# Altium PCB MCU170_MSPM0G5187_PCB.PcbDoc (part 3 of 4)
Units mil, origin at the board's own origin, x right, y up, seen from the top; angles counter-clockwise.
Board outline 2300 x 4450 mil, 4 copper layers (Top Layer, VCC Layer, GND Layer, Bottom Layer), stack 62.4 mil thick; 276 components, 190 nets, 913 pads, 323 vias.
Unrouted connection lines stored in the file: 4.
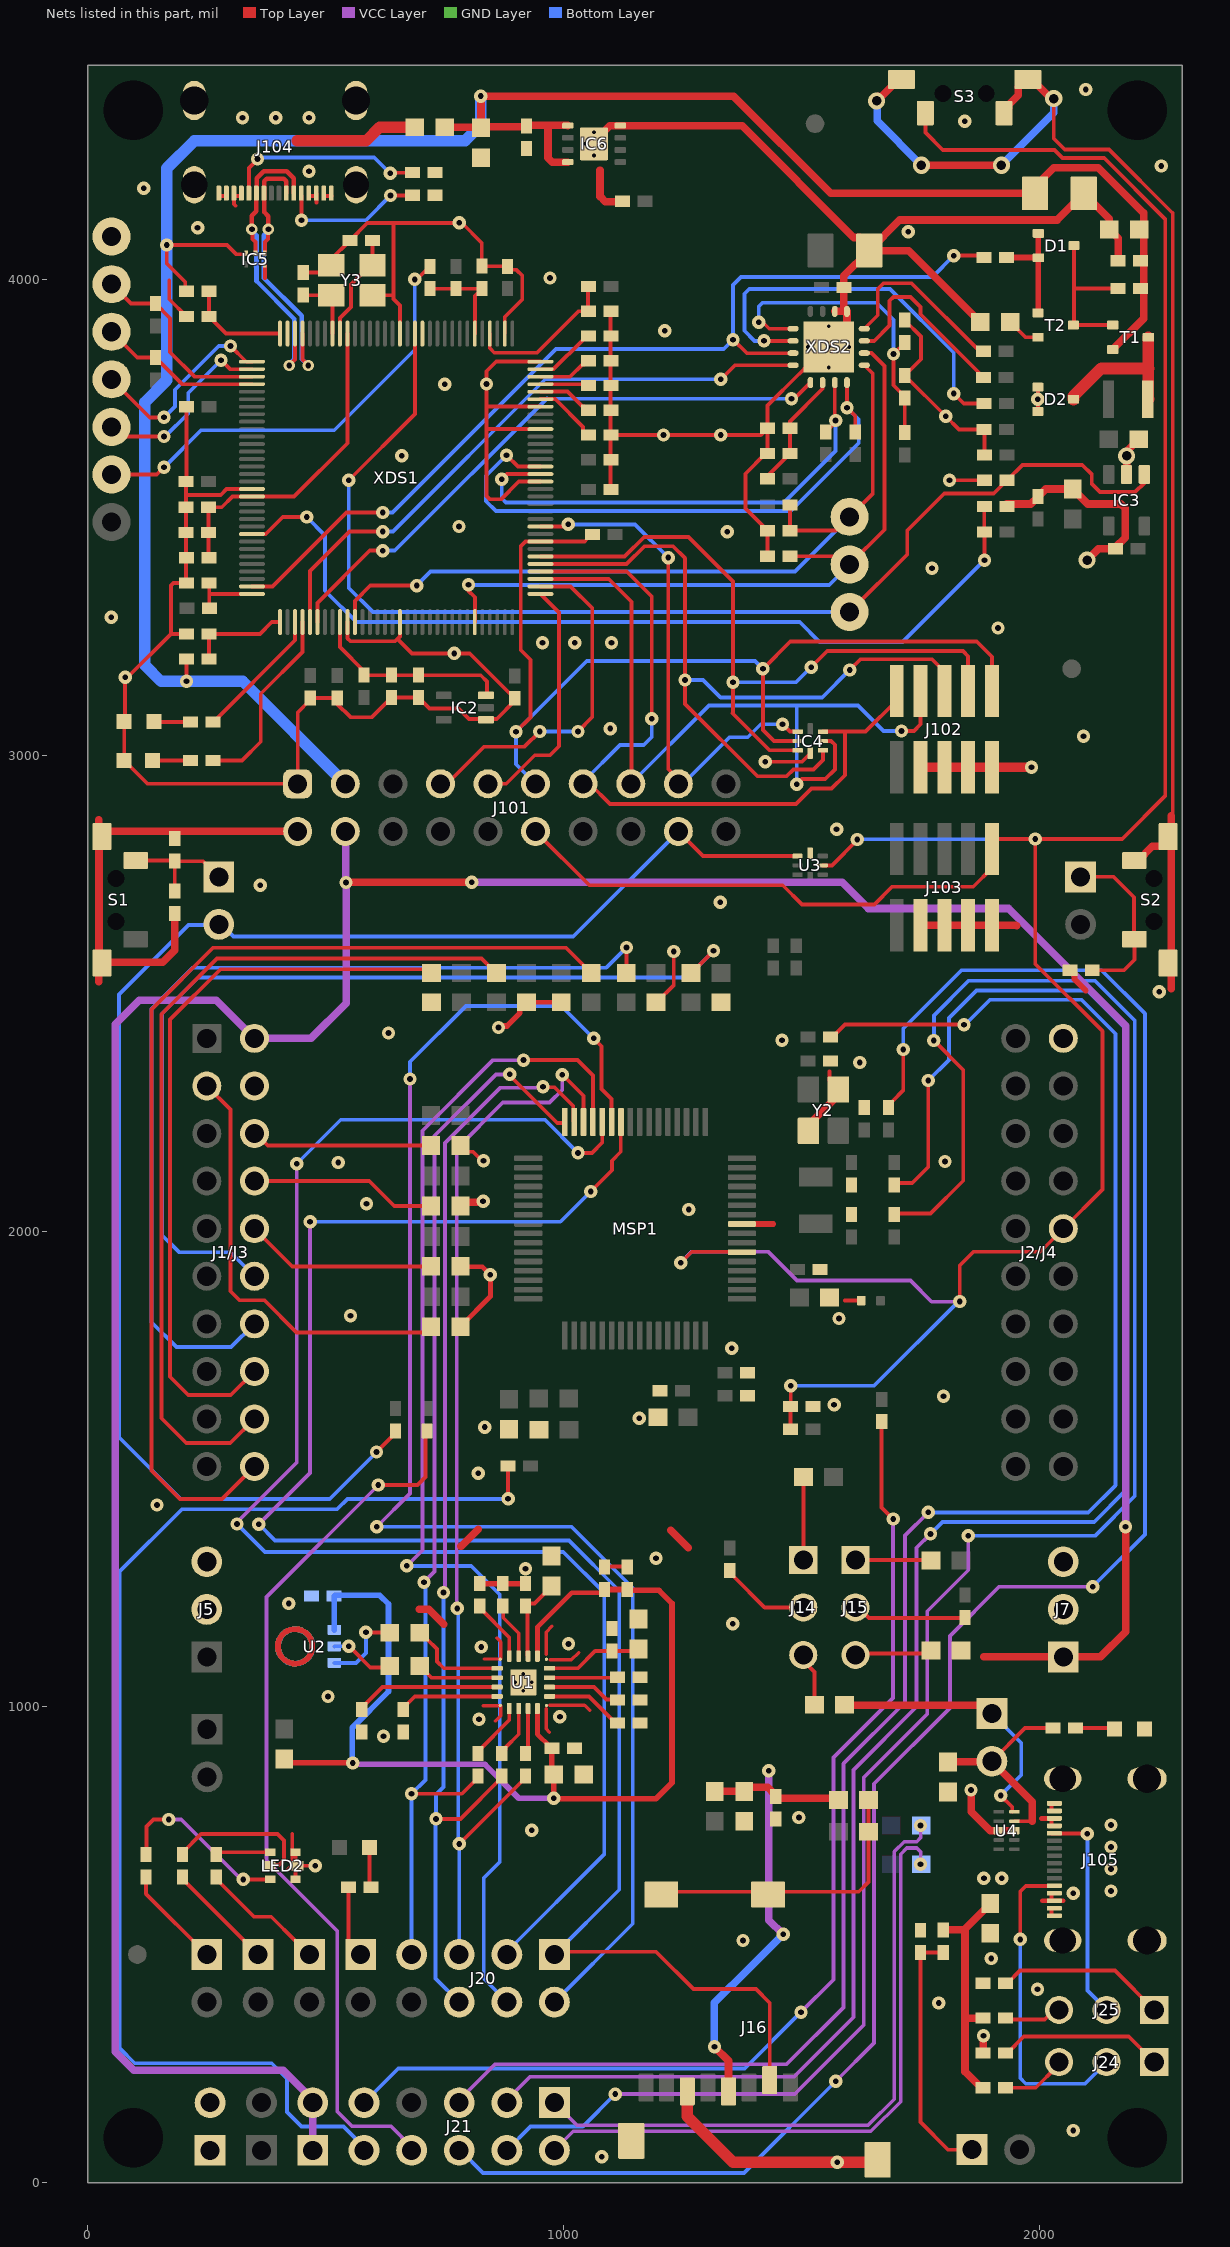
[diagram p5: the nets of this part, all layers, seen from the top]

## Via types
v1: diameter 28, hole 12, Top Layer to Bottom Layer, 291 vias
v2: diameter 19.68, hole 7.87, Top Layer to Bottom Layer, 9 vias
v3: diameter 36, hole 20, Top Layer to Bottom Layer, 8 vias
v4: diameter 24, hole 12, Top Layer to Bottom Layer, 4 vias
v5: diameter 24, hole 12, Top Layer to Bottom Layer, tented both sides, 4 vias
v6: diameter 19.68, hole 7.87, Top Layer to Bottom Layer, tented both sides, 4 vias
v7: diameter 28, hole 12, Top Layer to Bottom Layer, tented both sides, 2 vias
v8: diameter 39.37, hole 39.37, Top Layer to Bottom Layer, 1 vias

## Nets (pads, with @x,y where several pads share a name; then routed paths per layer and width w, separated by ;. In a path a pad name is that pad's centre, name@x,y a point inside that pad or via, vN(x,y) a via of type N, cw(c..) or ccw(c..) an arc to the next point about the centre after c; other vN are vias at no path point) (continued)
58_PB6_UC3_CS0_CTS: J16.2 J20.1 MSP1.58 | length 3766.4
  Top Layer w8: J20.1@980.54,479.62 986.32,485.4 1194.17,485.4 1272.67,406.9 1403.97,406.9 1433.07,377.8 J16.2@1433.07,215.7 ; v1(1056.83,2083.27) 1101.28,2127.72 1101.28,2147.83 1119.99,2166.55 MSP1.58@1119.99,2228.93
  VCC Layer w8: v1(359.28,1384.14) 360.02,1384.14 467.11,1491.23 v1(467.11,2019.48)
  Bottom Layer w8: v1(359.28,1384.14) 393.56,1349.87 1011.03,1349.87 1116.73,1244.16 1116.73,615.82 J20.1@980.54,479.62 ; v1(467.11,2019.48) 993.03,2019.48 v1(1056.83,2083.27)
59_PB7_UC3_POCI_RTS: J20.2 MSP1.59 | length 3190.3
  Top Layer w8: v1(1063.19,2404.94) 1079.75,2388.38 1079.75,2298.8 1100.81,2277.74 MSP1.59@1100.79,2229.41
  VCC Layer w8: v1(607.23,1378.75) 676.98,1448.51 676.98,2319.44 v1(677.08,2319.53)
  Bottom Layer w8: v1(607.23,1378.75) 1016.72,1378.75 1145.3,1250.17 1145.3,544.38 J20.2@980.54,379.62 ; v1(677.08,2319.53) 677.08,2355.79 794.55,2473.27 994.87,2473.27 v1(1063.19,2404.94)
60_PB8_UC3_PICO_TX: J20.3 MSP1.60 | length 3247.5
  Top Layer w8: v1(1030.16,2164.26) 1059.41,2164.26 1081.1,2185.95 MSP1.60@1081.1,2229.41
  VCC Layer w8: v1(313.4,1384.26) 313.4,1388.04 439.23,1513.87 v1(439.23,2141.48)
  Bottom Layer w8: v1(313.4,1384.26) 372.16,1325.51 999.25,1325.51 1085.49,1239.26 1085.49,690.51 880.54,485.55 J20.3@880.54,479.62 ; v1(439.23,2141.48) 531.68,2233.93 960.49,2233.93 v1(1030.16,2164.26)
61_PB9_UC3_SCK_RX: J20.4 MSP1.61 | length 2569.7
  Top Layer w8: v1(915.58,2359.31) 1029.37,2359.31 1061.42,2327.26 MSP1.61@1061.42,2229.41
  VCC Layer w8: v1(670.39,1296.38) 703.38,1329.36 703.38,2210.75 851.79,2359.16 915.43,2359.16 v1(915.58,2359.31)
  Bottom Layer w8: v1(670.39,1296.38) 805.75,1296.38 865.59,1236.54 865.59,673.73 831.98,640.13 831.98,429.39 880.54,380.84 J20.4@880.54,379.62
62_PB10_I2S_WCLK: J20.5 MSP1.62 R37.2 | length 2319.2
  Top Layer w8: v1(780.54,712.06) 919.61,851.13 R37.2@919.61,855.07 ; v1(997,2328.59) 997.68,2328.59 1041.73,2284.54 MSP1.62@1041.73,2229.41
  VCC Layer w8: v1(776.58,1206.98) 775.52,1208.03 775.52,2173.53 871.98,2269.99 970.45,2269.99 997,2296.54 v1(997,2328.59)
  Bottom Layer w8: v1(776.58,1206.98) 778.56,1205 778.56,714.04 v1(780.54,712.06) J20.5@780.54,479.62
63_PB11_I2S_BCLK: J20.6 MSP1.63 R39.2 | length 2380.1
  Top Layer w8: v1(731.75,764.61) 783.16,764.61 869.68,851.13 R39.2@869.68,855.07 ; v1(956.59,2303.23) 957.67,2302.15 980.5,2302.15 1020.14,2262.51 1020.14,2231.31 MSP1.63@1022.05,2229.41
  VCC Layer w8: v1@747.85,1240.91 750.72,1243.78 750.72,2184.85 867.24,2301.37 954.72,2301.37 v1(956.59,2303.23)
  Bottom Layer w8: v1(747.32,1240.37) 747.32,831.53 731.75,815.96 v1(731.75,764.61) 730.95,763.81 730.95,429.21 J20.6@780.54,379.62
64_PB12_I2S_AD0: J20.7 MSP1.64 R41.2 | length 2273.1
  Top Layer w8: v1(680.32,817.37) 786,817.37 811.94,843.32 819.76,851.13 R41.2@819.76,855.07 ; v1(886.78,2329.31) 886.78,2326.63 986.46,2226.96 1000.46,2226.96 1000.46,2227.5 MSP1.64@1002.36,2229.41
  VCC Layer w8: v1(706.48,1262.23) 728.53,1284.28 728.53,2200.27 857.57,2329.31 v1(886.78,2329.31)
  Bottom Layer w8: J20.7@680.54,479.62 680.43,479.73 680.43,817.27 v1(680.32,817.37) 709.39,846.44 709.39,1259.32 v1(706.48,1262.23)
+5V: J1/J3.21 J7.1 J17.1 J17.2 J22.1 J101.4 R12.2 R15.2 U4.5 | length 7574.5
  Top Layer w8: v1(1918.41,813.86) 1942.62,789.65 U4.5@1942.62,780
  Top Layer w16: v1(542.62,2732.62) 542.88,2732.89 806.86,2732.89 v1(807.13,2733.16) ; R12.2@1600,1003.78 1881.99,1003.78 J22.1@1900,985.77 ; 1882.48,1105 J7.1@2050,1105 2128.19,1105 2180.92,1157.73 v1(2180.92,1378.41)
  VCC Layer w16: J17.1@473.69,74 472.69,74 J17.2@472.69,168.18 472.69,174 410.44,236.26 96.43,236.26 57.81,274.88 57.81,2434.67 108.53,2485.39 269.61,2485.39 J1/J3.21@350,2405 468.98,2405 543.06,2479.08 543.06,2732.17 541.83,2733.41 541.83,2839.21 J101.4@541.04,2840 ; J17.1@497.17,49.52 J17.1@497.17,50.52 ; v1@807.29,2733 1585.48,2733 1640.49,2677.98 1934.75,2677.98 2180.92,2431.81 v1(2180.92,1378.41)
  Bottom Layer w8: J22.1@1900,985.77 1961.52,924.25 1961.52,856.97 v1(1918.41,813.86)
AREG: C28.2 C72.1 U1.17 | length 175.1
  Top Layer w8: C72.1@919.92,1210.96 924.24,1206.63 924.24,1107.58 U1.17@925.16,1106.66 ; C72.1@920.61,1211.65 926.28,1217.32 938.89,1217.32 959.77,1238.21 959.77,1238.45 967.72,1246.4 C28.2@974.71,1246.4
AVCCOUT: C55.1 R64.1 R65.2 XDS2.1 | length 692.2
  Top Layer w8: v1(1410,3910) 1418.48,3910 1432.09,3896.39 XDS2.1@1482.2,3896.39 ; R64.1@1717,3678.62 R65.2@1717,3751 1717,3753.89 1693.32,3777.58 v1(1693.32,3843.31) C55.1@1717,3867
  Bottom Layer w8: v1(1410,3910) 1410,3943 1418,3951 1657.64,3951 1693.32,3915.32 v1(1693.32,3843.31)
AVDD: C25.1 C27.1 C31.1 C73.1 C74.1 R38.1 U1.9 U1.16 U2.1 | length 2387.4
  Top Layer w10: U1.16@944.85,1106.66 944.85,1167.83 1017.14,1240.13 C73.1@1079.46,1240.13 ; U1.9@944.96,996.32 944.96,942.61 C74.1@970.65,916.92
  Top Layer w12: R38.1@412.97,890.35 420.83,882.49 556.36,882.49 v1(556.89,881.96) ; C74.1@975.1,913.16 975.1,862 C27.1@979.21,857.89 ; C27.1@981.95,857.89 979.45,855.39 v1(979.45,808.07) 980.65,806.87 1193.89,806.87 1227.73,840.72 1227.73,1217.59 1200.47,1244.86 1135.25,1244.86 C25.1@1133.72,1246.38 ; C73.1@1079.46,1240.13 C73.1@1085.71,1246.38 ; C73.1@1085.97,1246.63 C25.1@1133.47,1246.63
  VCC Layer w12: v1(556.89,881.96) 559.6,879.25 834.62,879.25 905.8,808.07 v1(979.45,808.07)
  Bottom Layer w10: v1@978.24,806.87 v1(979.45,808.07)
  Bottom Layer w12: U2.1@517.84,1161.82 517.84,1232.96 519.3,1234.42 613.67,1234.42 631.88,1216.21 631.88,1032.25 555.75,956.13 555.75,883.1 v1(556.89,881.96)
BSL_INVOKE: IC4.1 J101.17 XDS1.42 | length 1092.7
  Top Layer w8: XDS1.42@951.15,3480.64 1005.39,3480.64 v1(1009.88,3485.13) ; v1(1219.88,3415.34) 1219.88,2971.2 1241.04,2950.04 J101.17@1241.04,2940 ; v1(1460.08,3065) 1475.52,3049.56 IC4.1@1491.99,3049.56
  Bottom Layer w8: v1(1009.88,3485.13) 1150.09,3485.13 v1(1219.88,3415.34) ; J101.17@1241.04,2940 1251,2940 1348.76,3037.76 1387,3037.76 1414.24,3065 v1(1460.08,3065)
CC1: J24.2 J105.A5 | length 668.4
  Top Layer w8: v7(1959.42,511.35) 1959.42,612.17 1971.13,623.88 J105.A5@2025.17,623.88
  Bottom Layer w8: v7(1959.42,511.35) 1959.42,219.86 1971.28,208 2095.58,208 J24.2@2141.16,253.58
CC2: J25.2 J105.B5 | length 463
  Top Layer w8: J105.B5@2025.17,734.12 2025.43,733.86 2100.35,733.86 v7(2100.61,733.6)
  Bottom Layer w8: v7(2100.61,733.6) 2100.61,403.65 J25.2@2141.16,363.09
DCDCCAL0: R67.1 XDS2.12 | length 382.2
  Top Layer w8: XDS2.12@1631.8,3896.39 1660,3924.58 1660,3980 1672,3992 1731,3992 1873.8,3849.2 R67.1@1882.76,3849.2
DCDCCAL1: R66.1 XDS2.2 | length 846.7
  Top Layer w8: v1(1421.09,3870.8) XDS2.2@1482.2,3870.8 ; v1(1819.88,3760) 1840.88,3739 R66.1@1883.38,3739
  Bottom Layer w8: v1(1421.09,3870.8) 1401.2,3870.8 1380.01,3891.99 1380.01,3970.01 1390,3980 1685.86,3980 1819.88,3845.97 v1(1819.88,3760)
DCDCCAL2: R68.1 XDS2.11 | length 398.5
  Top Layer w8: XDS2.11@1631.8,3870.8 1652.8,3870.8 1685,3903 1685,3955 1693,3963 1729,3963 1750,3942 1750,3926.76 R68.1@1882.76,3794
DCDCIO0: XDS1.5 XDS2.4 | length 1301.6
  Top Layer w8: XDS1.5@466.9,3279.85 466.9,3386.9 550,3470 v1(620,3470) ; v1(1330.35,3790) 1359.97,3819.61 XDS2.4@1482.2,3819.61
  Bottom Layer w8: v1(620,3470) 641.3,3470 961.3,3790 v1(1330.35,3790)
DCDCIO1: XDS1.6 XDS2.5 | length 1268.8
  Top Layer w8: XDS1.6@482.65,3279.85 482.65,3320.15 ; 482.77,3320.15 482.77,3320.27 592.5,3430 v1(620,3430) ; v1(1479,3749) 1484.42,3749 XDS2.5@1518.61,3783.2
  Bottom Layer w8: v1(620,3430) 645,3430 965,3750 966,3749 v1(1479,3749)
DCDCPULSE: R75.2 XDS1.127 XDS2.3 | length 2033.7
  Top Layer w8: XDS1.127@344.85,3354.65 388.15,3354.65 543.5,3510 v1(620,3510) ; v1@1356,3874 1385.08,3844.92 1481.91,3844.92 XDS2.3@1482.2,3845.2 ; v1(1819.88,4050) 1879.38,4050 R75.2@1883.38,4046
  Bottom Layer w8: v1(620,3510) 640,3510 984,3854 1336.53,3854 v1(1356,3873.47) 1356,3988 1373,4005 1774.88,4005 v1(1819.88,4050)
DCDCRST: C59.1 R73.1 TP1.1 XDS1.11 XDS2.9 | length 1694.9
  Top Layer w8: XDS1.11@561.39,3279.85 561.39,3324.39 593.5,3356.5 v1(691,3356.5) ; R73.1@1475.62,3526 C59.1@1475.62,3472 1572,3472 TP1.1@1601,3501 1649.75,3549.75 1649.75,3801.66 XDS2.9@1631.8,3819.61
  Bottom Layer w8: v1(691,3356.5) 720.4,3385.9 1485.9,3385.9 TP1.1@1601,3501
DCDCTEST: R74.2 TP3.1 XDS1.27 XDS2.10 | length 1535.8
  Top Layer w8: v1(800,3358) 800,3345.3 813.35,3331.95 XDS1.27@813.35,3279.85 ; R74.2@1475.62,3418 1584,3418 TP3.1@1601,3401 1674,3474 1674,3818.34 1647.13,3845.2 XDS2.10@1631.8,3845.2
  Bottom Layer w8: v1(800,3358) 1558,3358 TP3.1@1601,3401
DREG: C29.2 C75.1 U1.14 | length 198.7
  Top Layer w8: U1.14@970.44,1081.07 1029.84,1081.07 1066.2,1117.44 1142.71,1117.44 1145.41,1120.14 C29.2@1145.41,1127.68
FMT0: R40.2 U1.19 | length 130.6
  Top Layer w8: R40.2@823.9,1211.65 823.9,1207.72 885.76,1145.86 U1.19@885.79,1106.66
GND: C1.2 C2.2 C3.2 C4.2 C5.2 C7.2 C8.1 C9.1 C10.2 C11.2 C12.2 C13.2 C14.1 C15.1 C16.1 C17.1 C18.1 C19.1 C20.1 C21.1 C22.1 C23.1 C24.1 C25.2 C26.1 C27.2 C28.1 C29.1 C31.2 C33.2 C34.2 C35.2 C36.2 C72.2 C73.2 C74.2 C75.2 C76.2 C77.2 J1/J3.22 J2/J4.20 J5.2 J5.3 J7.2 J7.3 J16.6 J16.9 J19.1 J19.2 J101.2 J103.3 J103.5 J103.7 J103.9 J105.1 J105.2 J105.3 J105.4 J105.A1 J105.A12 J105.B1 J105.B12 LED2.1 LED2.2 LED2.3 LED3.2 MSP1.41 R1.1 R3.1 R8.2 R40.1 R42.1 R43.1 R44.1 R46.1 R49.1 R50.1 S1.1 S1.2 S2.1 S2.2 S2.4 S3.1 S3.2 S3.3 U1.5 U1.10 U1.15 U1.20 U1.21 U2.4 U3.4 U4.3@1947.34,740.03 U4.8@1914.47,740.03 Y2.2 Y2.4 | length 7029.3
  Top Layer w7: 830.93,1002.47 866.25,1002.47 U1.5@866.79,1003.01 867.62,1002.17 867.62,981.7 856.26,970.34 ; 832.71,1100.58 U1.20@867.29,1100.58 ; 859.19,1144.81 867.54,1136.46 U1.20@867.54,1100.83 ; 963.1,995.77 963.1,953.55 970.17,946.48 ; 963.1,1110.39 963.1,1156.99 975.33,1169.23 ; 970.76,1003.79 1043.8,1003.79 1054.62,992.96 ; 971.81,1099.27 1016.47,1099.27 1031.45,1114.25
  Top Layer w8: 419.83,657.57 LED2.2@433.38,671.12 ; LED2.2@429.75,660.16 LED2.2@435.59,666 ; LED2.2@429.77,672.62 429.77,732.62 ; LED2.1@436.57,637.46 LED2.3@436.57,694.54 ; LED2.2@439.62,666.09 478.1,666.09 v1(478.19,666.18) ; C17.1@783.43,2179.75 796.53,2166.65 809.44,2166.65 v1@828.2,2147.89 ; C73.2@1083.92,1295.28 C25.2@1131.93,1295.28 ; C16.1@1194.31,2480.8 1195.29,2480.8 1231.54,2517.05 v1(1231.54,2587.6) ; 1558.86,2335.01 1558.86,2316 Y2.4@1577.5,2297.36 ; 1591.32,1853.76 R8.2@1625.44,1853.76 ; J105.B12@2025.17,560.89 J105.A1@2025.17,576.64 ; J105.B1@2025.17,781.36 J105.A12@2025.17,797.11 ; v3(2029.85,4379.85) 2030,4379.7 2030,4296 2053.13,4272.87 2146.29,4272.87 2280,4139.17 ; 2280,2879.16 2280,4139.17 ; 2280,4139.46 2280,4139.17
  Top Layer w10: C23.1@783.43,1798.83 783.43,1799.81 846.08,1862.47 846.08,1908.3 829.41,1924.97 784.26,1924.97 C21.1@783.43,1925.8 ; C20.1@921.69,2480.87 C22.1@995,2480.87
  Top Layer w11.81: R40.1@823.9,1258.9 C72.2@919.92,1258.9 ; 471.98,1127.17 ccw(c435.76,1127.17) 471.98,1127.17
  Top Layer w12: v1(863.12,2427.79) 866.19,2430.85 880.78,2430.85 908,2458.07 908,2468.17 920.7,2480.87 C20.1@921.69,2480.87 ; MSP1.41@1374.41,2014.84 1440.4,2014.84 ; C77.2@2063.62,2548.2 2067.56,2548.2 2073.37,2542.39 2073.37,2529.32 2097.08,2505.61
  Top Layer w15.75: v1(1856.17,825.21) 1856.17,780 1896.14,740.03 U4.3@1947.34,740.03
  Top Layer w16: 23.31,2523.62 23.31,2551.73 S1.2@34.74,2563.16 ; 23.34,2864.77 23.34,2840.3 S1.1@34.74,2828.91 ; S1.1@30.79,2824.95 23.38,2817.55 23.38,2574.52 S1.2@34.74,2563.16 ; S1.2@34.73,2577.06 S1.2@41.68,2570.1 ; S1.1@35.02,2828.63 S1.1@46.43,2840.03 ; S1.1@40.98,2840 J101.2@441.04,2840 J101.2@439.2,2838.16 ; R1.1@182.65,2665.07 182.65,2590.03 157.51,2564.88 36.46,2564.88 S1.2@34.74,2563.16 ; 696.11,1205 716.54,1205 748.09,1173.45 ; C19.1@783.43,2052.78 791.01,2060.36 828.4,2060.36 v1(830.69,2062.65) ; 784.32,1337.25 820.57,1373.5 ; 1225.13,1371.05 1262.08,1334.1 ; Y2.2@1520.45,2228.54 Y2.4@1568.53,2276.62 ; v3(1657.64,4375.12) 1661.46,4378.95 v3@1661.46,4385.15 ; v3@1658.11,4374.64 S3.2@1697.76,4414.29 ; S3.2@1701.11,4424.79 S3.2@1709.97,4424.79 ; J103.3@1750,2642.88 J103.5@1800,2642.88 J103.7@1850,2642.88 J103.9@1900,2642.88 1950.25,2642.88 1951.86,2641.28 ; v3@1752.32,4240.32 v3(1752,4240) v3(1920,4240) ; R50.1@1881.41,272.81 1881.92,273.31 1881.92,308.36 v1(1882.42,308.87) ; S3.3@1925.52,4353.93 1929.13,4353.93 1935.23,4360.03 1935.23,4367.03 1955.17,4386.97 1955.17,4404.25 S3.1@1975.71,4424.79 ; S3.1@1984.9,4418.95 1984.9,4417.98 1996.26,4406.62 1997.23,4406.62 2020.18,4383.67 2026.03,4383.67 v3(2029.85,4379.85) ; S2.4@2199.44,2778.68 2207.31,2778.68 2236.97,2808.33 2258.62,2808.33 2270.31,2820.02 S2.2@2270.31,2828.87 ; S2.1@2266.45,2558.13 2265.31,2558.13 S2.1@2270.31,2563.13 ; 2276.88,2509.14 S2.1@2276.88,2541.44 ; S2.1@2276.88,2581.55 2276.88,2872.41
  Top Layer w24: J16.6@1259.84,192.08 1259.84,139.2 1355.92,43.13 1654.59,43.13 J16.9@1659.84,48.38
  GND Layer w11.81: 471.98,1127.17 ccw(c435.76,1127.17) 471.98,1127.17
  Bottom Layer w16: v3(1657.64,4375.12) 1658.88,4373.87 1658.88,4333.12 v3(1752,4240) ; v3(1920,4240) 2029.85,4349.85 v3(2029.85,4379.85)
  other v1: 1575.24,43.13 1079.97,54.84 2071.08,109.71 1788.07,377.64 1995.63,406.9 1898.38,471.09 1376.75,509.12 933.04,740.75 1494.4,767.62 621.37,938.52 822.25,974.06 992.12,979.43 504.84,1022.02 826.98,1125.77 1010.21,1132.38 1355.48,1174.74 421.97,1217.29 919.79,1290.38 1194.17,1312.62 145.4,1424.21 820.5,1491.04 834.4,1588 1159.01,1606.89 1568.36,1634.86 1798.39,1653.09 1353.14,1753.82 1578.51,1816.15 552.16,1822.23 845.53,1908.3 1263.13,2045.42 585.56,2057.28 526.23,2144.03 1801.59,2146.33 831.61,2147.89 1622.2,2354.13 1458.86,2401.24 631.93,2416.39 2251.82,2502.77 1328.9,2690.8 362.59,2726.63 1573.61,2844.62
  other v6: 915.32,1033.83 897.6,1051.54 933.04,1051.54 915.32,1069.26
HOSTSCL: R70.1 XDS1.49 XDS2.7 | length 1051.7
  Top Layer w8: v1(870,3580.09) 880.78,3590.87 XDS1.49@951.15,3590.87 ; R70.1@1551,3678.98 1569.8,3697.77 XDS2.7@1569.8,3783.2
  Bottom Layer w8: v1(870,3580.09) 870,3540 879,3531 1463,3531 1571.5,3639.5 v1(1571.5,3703.35)
HOSTSDA: R69.1 XDS1.50 XDS2.8 | length 1241.2
  Top Layer w8: v1(880,3630.35) 903.73,3606.62 XDS1.50@951.15,3606.62 ; XDS2.8@1595.39,3783.2 v1(1595.39,3730) 1613,3712.39 R69.1@1613,3679.62
  Bottom Layer w8: v1(880,3630.35) 837.08,3587.44 837.08,3533.92 858,3513 1477.15,3513 1620.02,3655.87 1620.02,3705.37 v1(1595.39,3730)
IRSTN: R61.1 TP9.1 | length 936.7
  Top Layer w8: TP9.1@50,3590 145,3590 v1(160,3605) ; v1(687,4000) 691.24,4000 R61.1@718.87,4027.62
  Bottom Layer w8: v1(160,3605) 238,3683 517.85,3683 687,3852.15 v1(687,4000)
ITCK: R90.2 TP6.1 XDS1.100 | length 340.5
  Top Layer w8: TP6.1@50,3890 104,3836 R90.2@142,3836 198.15,3779.85 XDS1.100@344.85,3779.85
ITDI: TP8.1 XDS1.98 | length 402
  Top Layer w8: TP8.1@50,3690 70,3670 v1(160,3670) ; v1(280,3830) 298.65,3811.35 XDS1.98@344.85,3811.35
  Bottom Layer w8: v1(160,3670) 162.52,3670 211,3718.48 211,3761 v1(280,3830)
ITDO: TP7.1 XDS1.97 | length 424.3
  Top Layer w8: TP7.1@50,3790 130,3710 v1(160,3710) ; v1(300,3860) 332.91,3827.09 XDS1.97@344.85,3827.09
  Bottom Layer w8: v1(160,3710) 183,3733 183,3768 275,3860 v1(300,3860)
ITMS: R89.2 TP5.1 XDS1.99 | length 417.2
  Top Layer w8: TP5.1@50,3990 90.62,3949.38 R89.2@142,3949.38 173,3918.38 173,3847 224.4,3795.6 XDS1.99@344.85,3795.6
L_2_PB14_A0_21: J1/J3.23 R28.1 | length 381.7
  Top Layer w8: J1/J3.23@350,2205 352.99,2205 378.24,2179.75 R28.1@721.22,2179.75
L_3_PB15_A0_20: J1/J3.24 R30.1 | length 392.8
  Top Layer w8: J1/J3.24@350.13,2105.13 591.57,2105.13 643.92,2052.78 R30.1@721.22,2052.78
L_4_PB16_A0_19: J1/J3.25 R32.1 | length 403.7
  Top Layer w8: J1/J3.25@350,2005 429.69,1925.31 R32.1@720.73,1925.31
L_5_PA12_I2S_BCLK_A0_18: J1/J3.28 R31.1 | length 1561.3
  Top Layer w8: J1/J3.28@350,1705 300.42,1655.42 211.19,1655.42 172.74,1693.87 172.74,2444.65 278.48,2550.39 714.28,2550.39 R31.1@722.38,2542.28
L_6_PA13_I2S_AD0_A0_17: J1/J3.29 R33.1 | length 1851.9
  Top Layer w8: J1/J3.29@350,1605 299.43,1554.43 206.9,1554.43 154.67,1606.66 154.67,2455.55 271.69,2572.57 827.41,2572.57 857.71,2542.28 R33.1@858.69,2542.28
L_7_PA14_I2S_AD1_A0_16: J1/J3.30 R35.1 | length 2239.1
  Top Layer w8: J1/J3.30@350,1505 282.02,1437.02 193.49,1437.02 133.53,1496.98 133.53,2465.75 263.31,2595.53 1004.74,2595.53 1042.31,2557.96 1042.31,2556.98 1057.01,2542.28 R35.1@1058,2542.28
L_8_PA15_I2S_WCLK_A0_15: J1/J3.27 R29.1 | length 2021.7
  Top Layer w8: R29.1@1131.31,2542.28 1132.04,2543 v1(1132.04,2595.92)
  Bottom Layer w8: J1/J3.27@350,1805 301.14,1756.14 186.23,1756.14 133.87,1808.49 133.87,2466.39 221.05,2553.56 1089.68,2553.56 v1(1132.04,2595.92)
L_9_PA16_I2S_MCLK_A0_14: J1/J3.26 R36.1 | length 1976
  Top Layer w8: R36.1@1267.62,2542.34 1268.61,2542.34 1314.74,2588.48 v1(1314.74,2589.19)
  Bottom Layer w8: J1/J3.26@350,1905 299.36,1955.64 191.41,1955.64 156.57,1990.48 156.57,2457.51 232.21,2533.15 1259.53,2533.15 1314.74,2588.36 v1(1314.74,2589.19)
L_11_PA18_BSL_Invoke: J8.2 J101.18 R22.1 U3.5 | length 3237
  Top Layer w8: v1(606.56,1535.7) 606.9,1535.7 646.74,1575.54 R22.1@646.74,1579.48 ; J101.18@1241.04,2840 1292.87,2788.17 U3.5@1491.35,2788.17
  Bottom Layer w8: v1@606.56,1534.99 508.42,1436.85 195.15,1436.85 65.41,1566.59 65.41,2496.95 211.68,2643.23 273.96,2643.23 J8.2@275.18,2644.45 280.92,2644.45 306.19,2619.18 1020.22,2619.18 J101.18@1241.04,2840
L_26_PA25_A0_2: J1/J3.2 R34.1 | length 914.3
  Top Layer w8: J1/J3.2@250,2305 299.73,2255.27 299.73,1873.5 318.5,1854.72 371.16,1854.72 438.83,1787.05 709.45,1787.05 R34.1@721.22,1798.83
L_62_PB10_I2S_WCLK: R37.1 U1.8 | length 96
  Top Layer w8: R37.1@919.61,902.31 925.12,907.83 U1.8@925.12,996.03
L_63_PB11_I2S_BCLK: R39.1 U1.7 | length 108.9
  Top Layer w8: R39.1@869.68,902.31 877.49,910.12 877.49,914.38 905.48,942.36 U1.7@905.48,996.43
L_64_PB12_I2S_AD0: R41.1 U1.6 | length 121.5
  Top Layer w8: R41.1@819.76,902.31 819.76,906.25 885.79,972.29 U1.6@885.79,996.43
LS_17_PA21_VREF-: J21.8 R20.1 | length 1866.4
  Top Layer w8: v1(610.26,1466.41) 692.97,1466.41 709.39,1482.82 709.39,1576.12 R20.1@712.75,1579.48
  VCC Layer w8: v1@610.26,1465.94 375.21,1230.89 375.21,677.77 524.25,528.73 524.25,149.86 555.48,118.63 636.91,118.63 J21.8@680.54,75
LS_24_PA23_VREF+: J21.10 R21.1 | length 2591.6
  Top Layer w8: R21.1@882.87,1506.26 883.24,1505.89 v1(883.24,1437.18)
  Bottom Layer w8: J21.10@580.54,75 537.58,117.95 449.13,117.95 418.64,148.44 418.64,218.81 386.4,251.06 98.59,251.06 66.76,282.88 66.76,1284.4 197.7,1415.34 523.96,1415.34 545.81,1437.18 v1(883.24,1437.18)
LS_42_PA2_ROSC: J21.9 R9.1 | length 2337.1
  Top Layer w8: R9.1@1667.95,1608.05 1667.95,1419.26 v1(1692.44,1394.77)
  VCC Layer w8: v1(1498.89,358.5) 1566.96,426.57 1566.96,893.46 1692.44,1018.94 v1(1692.44,1394.77)
  Bottom Layer w8: J21.9@580.54,168.18 652.52,240.17 1380.56,240.17 v1(1498.89,358.5)
LS_43_PA3_LFXIN: J21.4 R10.1 | length 4406.9
  Top Layer w8: R10.1@1694.83,2029.79 1701.63,2036.59 1770.7,2036.59 1839.93,2105.82 1839.93,2338.72 v1(1778.01,2400.64)
  VCC Layer w8: v1(1108.38,186.25) 1485.73,186.25 1630.76,331.27 1630.76,851.88 1764.09,985.22 1764.09,1200.96 1850.27,1287.14 v1(1850.27,1359.47)
  Bottom Layer w8: J21.4@888.41,68.18 J21.4@880.54,68.18 930.54,118.18 1040.31,118.18 v1(1108.38,186.25) ; v1(1778.01,2400.64) 1778.01,2453 1851.09,2526.09 2116.72,2526.09 2200.21,2442.61 2200.21,1442.9 2116.78,1359.47 v1(1850.27,1359.47)
LS_44_PA4_LFXOUT: J21.3 R11.1 | length 4146.5
  Top Layer w8: R11.1@1694.83,2100.72 1732.68,2100.72 1766.24,2134.29 v1(1766.24,2316.33)
  VCC Layer w8: J21.3@880.54,174 929.09,222.55 1484.13,222.55 1609.21,347.64 1609.21,867.72 1741.7,1000.21 1741.7,1334.41 v1(1770.85,1363.56)
  Bottom Layer w8: v1(1766.24,2316.33) 1809.55,2359.63 1809.55,2447.5 1867.66,2505.61 2101.17,2505.61 2179.78,2427.01 2179.78,1453.48 2114.92,1388.62 1795.91,1388.62 v1(1770.85,1363.56)
LS_45_PA5_HFXIN: J21.6 R14.1 | length 4293.7
  Top Layer w8: R14.1@1682.61,2259.81 1690.42,2267.62 1690.42,2272.1 1713.49,2295.17 v1(1713.49,2381.47)
  VCC Layer w8: v1(1571.81,213.34) 1652.3,293.83 1652.3,838.35 1811.61,997.65 1811.61,1149.17 1915.05,1252.6 v1(2111.73,1252.6)
  Bottom Layer w8: J21.6@780.54,68.18 783.06,68.18 830.73,20.5 1378.97,20.5 v1(1571.81,213.34) ; v1(1713.49,2381.47) 1713.49,2425.31 1836.37,2548.2 2130.13,2548.2 2221.44,2456.89 2221.44,1362.31 v1(2111.73,1252.6)
LS_46_PA6_HFXOUT: J21.5 R17.1 | length 4034.4
  Top Layer w8: R17.1@1560.98,2408.02 1564.92,2408.02 1591.27,2434.37 1840.62,2434.37 v1(1841.35,2433.64)
  VCC Layer w8: J21.5@780.54,167.74 J21.5@783.66,170.87 ; J21.5@780.54,174 855.38,248.85 1468.6,248.85 1587.93,368.18 1587.93,880.7 1717.14,1009.9 1717.14,1359.89 v1(1766.47,1409.21)
  Bottom Layer w8: v1(1766.47,1409.21) 1767.22,1408.46 2102.4,1408.46 2159.56,1465.62 2159.56,2414.58 2088.05,2486.08 1896.19,2486.08 1843.75,2433.64 v1(1841.35,2433.64)
M_SZ: R42.2 U1.13 | length 143
  Top Layer w8: U1.13@970.44,1061.39 1112.09,1061.39 R42.2@1113.06,1062.36
MD0: R44.2 U1.12 | length 153.7
  Top Layer w8: U1.12@970.44,1041.7 1063.52,1041.7 1089.78,1015.44 1111.75,1015.44 R44.2@1112.84,1014.35
MD1_MCLK: R43.2 U1.11 | length 165.5
  Top Layer w8: U1.11@970.44,1022.02 1053.18,1022.02 1080.62,994.57 ; 1080.67,994.57 1108.91,966.34 R43.2@1112.84,966.34
MSP_VBUS: C35.1 C36.1 J22.2 J105.A4 J105.A9 J105.B4 J105.B9 R45.1 R47.2 R48.2 R51.1 U4.4 | length 1067.1
  Top Layer w8: J22.2@1900,885.77 1969.84,955.6 R51.1@2028.75,955.6 ; U4.4@1947.34,759.72 1985.07,759.72 ; J105.B9@2025.17,592.39 J105.A4@2025.17,608.13 ; J105.B4@2025.17,749.87 J105.A9@2025.17,765.61
  Top Layer w10: 2003.67,765.61 2025.17,765.61 J105.A9@2031.17,765.61 ; 2005.67,592.39 2050,592.39 ; J105.B9@2025.17,592.39 J105.B9@2031.17,592.39
  Top Layer w16: R45.1@1797.79,531.14 1797.9,531.25 1841.72,531.25 C35.1@1896.49,586.03 ; C36.1@1807.96,884.21 1808.74,884.99 1899.22,884.99 J22.2@1900,885.77 1985.07,800.7 1985.07,759.72 ; 1843.56,533.1 1843.56,345.98 ; R48.2@1879.02,345.98 1843.56,345.98 ; R47.2@1881.41,199.64 1877.48,199.64 1843.56,233.55 1843.56,345.98
  other v1: 2070.84,608.42 2150.34,613.04 1883.18,640 1920.41,640 2150.34,659.34 2150.34,705.65 2150.34,751.95
NetC30_1: C30.1 U1.1 | length 209
  Top Layer w8: C30.1@698.15,1156.99 698.64,1156.99 713.34,1142.29 713.34,1141.81 733.75,1121.4 733.75,1095.3 747.96,1081.09 U1.1@860.2,1081.07
NetC30_2: C30.2 U2.3 | length 169
  Top Layer w8: v1@584.88,1156.62 634.05,1156.62 C30.2@634.66,1156
  Bottom Layer w8: U2.3@517.84,1092.52 563.69,1092.52 584.41,1113.25 v1(584.41,1157.09)
NetC32_1: C32.1 U1.2 | length 173
  Top Layer w8: C32.1@697.66,1085.64 698.87,1085.64 713.34,1071.16 713.34,1070.49 722.44,1061.39 U1.2@860.2,1061.39
NetC32_2: C32.2 U2.2 | length 127.3
  Top Layer w8: v1(548.64,1127.7) 593.38,1082.96 622.43,1082.96 C32.2@625.22,1085.76
  Bottom Layer w8: U2.2@517.84,1127.17 518.11,1127.43 548.38,1127.43 v1(548.64,1127.7)
NetC33_1: C33.1 U1.3 | length 306.3
  Top Layer w8: C33.1@575.73,994.51 575.73,998.45 583.54,1006.26 618.99,1041.7 U1.3@860.2,1041.7
NetC34_1: C34.1 U1.4 | length 210.8
  Top Layer w8: C34.1@663.11,994.51 663.11,998.45 670.92,1006.26 671.13,1006.26 686.89,1022.02 U1.4@860.2,1022.02
NetC37_1: C37.1 R56.2 XDS1.96 | length 217.1
  Top Layer w8: R56.2@254.62,3975 C37.1@254.62,3922 290.47,3886.15 XDS1.96@403.91,3886.15
NetC44_1: C44.1 R59.1 R61.2 XDS1.70 | length 209.4
  Top Layer w8: R61.2@718.87,3980.38 828,3980.38 813.35,3965.73 XDS1.70@813.35,3886.15
NetC47_1: C47.1 C48.1 C49.1 XDS1.87 XDS1.115 | length 684.7
  Top Layer w8: C49.1@254.62,3415 253.62,3416 C48.1@253.62,3468 C47.1@253.62,3521 281.37,3521 304,3543.63 XDS1.115@344.85,3543.63 433.63,3543.63 545.64,3655.64 XDS1.87@545.64,3886.15
NetC50_1: C50.1 C51.1 IC2.3 R62.1 XDS1.9 | length 425.8
  Top Layer w8: XDS1.9@529.89,3279.85 529.89,3227.11 580.4,3176.6 R62.1@580.4,3168.26 C50.1@638,3168.26 C51.1@695,3168.26 825.74,3168.26 838.79,3155.21 IC2.3@838.79,3125.75
NetC52_1: C52.1 R63.1 XDS1.68 | length 329
  Top Layer w8: XDS1.68@844.85,3886.15 844.85,3855.15 854,3846 944,3846 1031,3933 1051.04,3933 R63.1@1051.04,3985
NetC53_1: C53.1 XDS1.88 Y3.3 | length 227.2
  Top Layer w8: XDS1.88@529.89,3886.15 529.89,3919.05 553,3942.16 553,3989.17 593.33,4029.5 Y3.3@598.31,4029.5 598.31,4081.66 C53.1@598,4081.97
NetC54_1: C54.1 XDS1.89 Y3.1 | length 140.7
  Top Layer w8: C54.1@452.72,3967.38 453.6,3966.5 Y3.1@511.69,3966.5 514.14,3964.06 XDS1.89@514.14,3886.15
NetC58_1: C58.1 R71.1 R72.2 XDS2.6 | length 250.2
  Top Layer w8: R71.1@1428.38,3581 1428.38,3586.76 R72.2@1475.62,3634 C58.1@1475.62,3687 1475.62,3701.62 1544.2,3770.2 XDS2.6@1544.2,3783.2
NetC76_1: C76.1 J8.1 R1.2 S1.3 | length 243.3
  Top Layer w8: S1.3@116.49,2778.71 C76.1@178.34,2778.71 ; C76.1@178.34,2782.64 183.31,2782.64 C76.1@183.31,2777.26 ; R1.2@182.65,2712.31 C76.1@182.65,2777.26 242.38,2777.26 J8.1@275.18,2744.45
NetC77_1: C77.1 J10.1 S2.3 | length 361
  Top Layer w8: J10.1@2086.38,2744.45 2155.76,2744.45 2198.8,2701.41 2198.8,2613.96 S2.3@2199.44,2613.32 2199.44,2570.13 2177.5,2548.2 C77.1@2109.31,2548.2
NetD1_1: D1.1 D1.2 R75.1 T2.1 | length 234.7
  Top Layer w12: R75.1@1930.62,4046 1997.14,4046 D1.2@1997.6,4045.54 ; T2.1@1996.6,3929.59 1997.6,3930.59 D1.2@1997.6,4045.54 ; D1.1@1997.6,4096.72 D1.2@1997.6,4045.54
NetD1_3: D1.3 R76.1 T1.1 T2.3 | length 343.5
  Top Layer w8: D1.3@2072.4,4071.13 2072.4,3982 ; T1.1@2154,3904 T2.3@2071.4,3904 2072.4,3905 2072.4,3982 ; R76.1@2165.38,3981 2073.4,3981 2072.4,3982
NetD2_3: D2.3 L1.1 T1.3 | length 318.9
  Top Layer w24: L1.1@2228.8,3749.06 2228.8,3813 T1.3@2228.8,3878.41
  Top Layer w25: D2.3@2071.4,3748 2071.4,3754.33 2130.07,3813 2228.8,3813 ; L1.1@2227.74,3748 L1.1@2228.8,3749.06
NetJ9_1: J9.1 R4.1 | length 152.2
  Top Layer w8: R4.1@547.7,621.12 547.7,505.44 J9.1@573.53,479.62
NetJ11_1: J11.1 R5.1 | length 215.3
  Top Layer w8: R5.1@122.5,642.07 122.5,607.12 J11.1@250,479.62
NetJ12_1: J12.1 R6.1 | length 228.1
  Top Layer w8: R6.1@199.17,642.38 199.17,638.44 328.53,509.08 328.53,508.1 J12.1@357.01,479.62
NetJ13_1: J13.1 R7.1 | length 264.4
  Top Layer w8: R7.1@270,642.07 270,638.13 349.24,558.89 385.58,558.89 436.37,508.1 J13.1@464.85,479.62
NetJ14_1: J14.1 R16.1 | length 175.9
  Top Layer w8: J14.1@1503.61,1307.5 1504,1307.89 R16.1@1504,1483.28
NetJ14_3: J14.3 R12.1 | length 116.9
  Top Layer w8: J14.3@1503.61,1108.99 1503.61,1097.02 1526.99,1073.64 R12.1@1526.99,1004.64 ; R12.1@1535.68,1005.8 1536.98,1004.49 R12.1@1536,1004.49
NetJ15_1: J15.1 R19.1 | length 146.6
  Top Layer w8: J15.1@1613.12,1308.99 1754.57,1308.99 R19.1@1758.11,1305.46 ; R19.1@1758.18,1305.53 R19.1@1758.25,1305.46
NetJ15_3: J15.3 R15.1 | length 163.1
  Top Layer w8: J15.3@1613.12,1108.99 1616.15,1112.02 1765.48,1112.02 R15.1@1772.21,1118.75
NetJ21_1: J21.1 R91.2 | length 1369.6
  VCC Layer w7.4: J21.1@980.54,168.18 1027.44,121.27 1640.14,121.27 1694.66,175.8 1694.66,696.02 1715.47,716.83 1742.13,716.83 1750,724.7 v1(1750,750.75)
NetJ21_2: J21.2 R92.2 | length 1366.8
  VCC Layer w7.4: J21.2@980.54,68.18 1020.23,107.87 1645.69,107.87 1708.06,170.25 1708.06,690.47 1721.02,703.43 1742.38,703.43 1750,695.81 v1(1750,669.51)
NetJ23_1: J23.1 R45.2 R46.2 | length 537.5
  Top Layer w8: R45.2@1797.79,485.3 1796.38,483.9 1749.78,483.9 R46.2@1749.78,483.34 1749.78,127.68 1808.02,69.43 J23.1@1858.32,69.43
NetJ24_1: J24.1 R50.2 | length 348.9
  Top Layer w8: R50.2@1928.66,272.81 1932.59,272.81 1966.86,307.07 2187.68,307.07 J24.1@2241.16,253.58
NetJ24_3: J24.3 R47.1 | length 126.7
  Top Layer w8: R47.1@1929.18,199.64 1992.28,199.64 2036.65,244 J24.3@2037.5,244
NetJ25_1: J25.1 R49.2 | length 357.7
  Top Layer w8: R49.2@1928.66,419.16 1932.59,419.16 1959.17,445.73 2158.52,445.73 J25.1@2241.16,363.09
NetJ25_3: J25.3 R48.1 | length 122.3
  Top Layer w8: R48.1@1928.66,345.98 1931.92,342.73 2010.95,342.73 2031.32,363.09 J25.3@2041.16,363.09
NetJ104_A5: J104.A5 R86.2 | length 302.2
  Top Layer w8: J104.A5@448.82,4175.17 448.96,4175.03 448.96,4124.62 v1(449.11,4124.47) ; v1(636.27,4176.39) 636.5,4176.61 678.6,4176.61 R86.2@678.82,4176.39
  Bottom Layer w8: v1(449.11,4124.47) 584.36,4124.47 v1(636.27,4176.39)
NetJ104_B5: J104.B5 R88.2 | length 426.6
  Top Layer w8: J104.B5@338.61,4175.2 338.61,4234.24 356.65,4252.28 v1(356.65,4252.96) ; v1(635.27,4223.06) 636.16,4223.95 681.07,4223.95 R88.2@681.96,4224.85
  Bottom Layer w8: v1(356.65,4252.96) 360.14,4256.45 601.88,4256.45 v1(635.27,4223.06)
NetLED1_2: LED1.2 R4.2 | length 85
  Top Layer w8: LED1.2@592.06,704.89 592.06,624 R4.2@594.95,621.12
NetLED2_4: LED2.4 R5.2 | length 378.3
  Top Layer w8: R5.2@122.5,689.32 123.26,690.08 123.26,748.85 137.94,763.53 v1(169.99,763.53) ; v1(326.72,637.46) LED2.4@383.43,637.46
  VCC Layer w8: v1(169.99,763.53) 196.48,763.53 322.56,637.46 v1(326.72,637.46)
NetLED2_5: LED2.5 R6.2 | length 315.9
  Top Layer w8: R6.2@199.17,689.62 199.17,693.56 238.17,732.56 398.91,732.56 412.48,718.99 412.48,678.47 401.57,667.55 382.03,667.55 LED2.5@381.02,666.55
NetLED2_6: LED2.6 R7.2 | length 115.6
  Top Layer w8: R7.2@270,689.32 275.23,694.54 LED2.6@383.43,694.54
NetLED3_1: LED3.1 R51.2 | length 85.3
  Top Layer w8: R51.2@2075.99,955.6 2150.7,955.6 LED3.1@2158.2,948.11
NetLED101_1: LED101.1 R57.1 | length 78.9
  Top Layer w8: LED101.1@136.65,3070.41 137.06,3070 R57.1@215.38,3070
NetLED102_1: LED102.1 R58.1 | length 79.9
  Top Layer w8: LED102.1@135.53,2989 R58.1@215.38,2989
NetR52_1: R52.1 XDS1.63 | length 128.9
  Top Layer w8: XDS1.63@951.15,3811.35 978.73,3811.35 1040.29,3872.91 1040.29,3873.19 1048.1,3881 R52.1@1051.04,3881
NetR53_1: R53.1 XDS1.62 | length 113.7
  Top Layer w8: XDS1.62@951.15,3795.6 1013.7,3795.6 1039.29,3821.19 1043.23,3821.19 R53.1@1051.04,3829
NetR54_1: R54.1 XDS1.61 | length 112.4
  Top Layer w8: XDS1.61@951.15,3779.85 1059.53,3779.85 R54.1@1062.38,3777
NetR55_1: R55.1 XDS1.60 | length 116.1
  Top Layer w8: XDS1.60@951.15,3764.1 1008,3764.1 1039.29,3732.81 1043.23,3732.81 R55.1@1051.04,3725
NetR57_2: R57.2 XDS1.3 | length 282.2
  Top Layer w8: R57.2@262.62,3070 263.91,3070 435.4,3241.5 XDS1.3@435.4,3279.85
NetR58_2: R58.2 XDS1.4 | length 404.9
  Top Layer w8: R58.2@262.62,2989 324,2989 363.31,3028.31 363.31,3129.31 451.15,3217.15 XDS1.4@451.15,3279.85
NetR60_2: R60.2 XDS1.59 | length 137.5
  Top Layer w8: XDS1.59@951.15,3748.35 982.24,3748.35 1040.55,3690.04 1040.55,3680.81 1048.37,3673 R60.2@1052.04,3673
NetR80_2: R80.2 T2.2 | length 71.4
  Top Layer w8: R80.2@1938.5,3910.41 1970.5,3878.41 T2.2@1996.6,3878.41
PA0: J14.2 R13.2 | length 188.7
  Top Layer w8: R13.2@1349.18,1286.19 1349.18,1282.25 1356.99,1274.44 1422.44,1208.99 J14.2@1503.61,1208.99
PA1: J15.2 R18.2 | length 239.6
  Top Layer w8: J15.2@1613.12,1208.99 1619.35,1208.99 1641.41,1186.93 1842.13,1186.93 R18.2@1843.19,1187.99
R\S\T\: C5.1 J2/J4.16 J101.12 J103.10 MSP1.38 R2.1 S3.4 U3.2 | length 6347.4
  Top Layer w8: J101.12@941.04,2840 1054.34,2726.7 1460.47,2726.7 1500.85,2686.32 1652.99,2686.32 1690.28,2723.61 1860.85,2723.61 1900,2762.76 J103.10@1900,2803.12 1900,2813.36 1910.57,2823.93 v1(1991.16,2823.93) ; v1(1245.96,1933.55) 1269.09,1956.68 1373.52,1956.68 MSP1.38@1374.41,1955.79 ; R2.1@1476.66,1583.28 C5.1@1476.66,1631.29 1477.13,1631.75 v1(1477.13,1674.76) ; U3.2@1544.5,2768.49 1563.78,2768.49 1616.91,2821.62 v1(1616.91,2822.91) ; S3.4@1760.16,4347.44 1760.16,4308.6 1796.77,4272 2031.55,4272 2048.68,4254.87 2136.13,4254.87 2264.13,4126.87 2264.13,2914.2 2173.86,2823.93 v1(1991.16,2823.93) ; v1(1832.51,1852.13) 1832.51,1927.54 1861.59,1956.62 2001.62,1956.62 J2/J4.16@2050,2005 2132.2,2087.2 2132.2,2420.12 1991.16,2561.15 v1(1991.16,2823.93)
  VCC Layer w8: v1(1245.96,1933.55) 1269.13,1956.72 1429.75,1956.72 1490.6,1895.87 1728.85,1895.87 1773.38,1851.34 1831.72,1851.34 v1(1832.51,1852.13)
  Bottom Layer w8: v1(1477.13,1674.76) 1652.53,1674.76 1829.9,1852.13 v1(1832.51,1852.13) ; v1(1616.91,2822.91) 1617.42,2823.42 1990.65,2823.42 v1(1991.16,2823.93)
REF_MAIN_LDO: R79.1 R82.2 XDS1.128 | length 143.9
  Top Layer w8: R82.2@254.62,3362 255.24,3361.38 255.24,3341.5 ; R79.1@255.24,3309 255.24,3341.5 ; XDS1.128@344.85,3338.91 257.84,3338.91 255.24,3341.5
REF_TARGET_VCC: R78.1 R81.2 XDS1.120 | length 1915.4
  Top Layer w8: XDS1.120@344.85,3464.89 373.97,3464.89 409.58,3500.5 v1(460,3500.5) ; R81.2@1884,3523 1884,3469.38 R78.1@1884.38,3469 v1(1884.38,3410)
  Bottom Layer w8: v1(460,3500.5) 498.64,3461.86 498.64,3345.77 564.56,3279.85 1496.15,3279.85 1538,3238 1712.38,3238 v1(1884.38,3410)
SD_VDD: C14.2 C15.2 J16.4 R23.2 R26.2 | length 1022.4
  Top Layer w16: R23.2@1307.7,811.91 R23.2@1307.7,812.86 ; v1(1316.85,286.04) 1346.46,256.43 J16.4@1346.46,192.08 ; R23.2@1317.59,822.41 C15.2@1379.42,822.41 1387.93,830.91 1428.57,830.91 C14.2@1437.94,821.54 ; C14.2@1444.97,811.04 1448.2,807.81 1574.38,807.81 R26.2@1577.61,804.58
  VCC Layer w16: v1(1431.27,866.03) 1431.27,552.05 v1(1461.19,522.13)
  Bottom Layer w16: v1(1316.85,286.04) 1316.85,377.79 1392.91,453.85 v1(1461.19,522.13)
SW_DETECT: J16.10 R26.1 R27.2 | length 616.7
  Top Layer w8: J16.10@1205.12,611.46 1429.53,611.46 1620.25,611.46 1640.6,631.81 R27.2@1640.6,737.57 R26.1@1640.6,804.58
VBUS1: J104.A4 J104.A9 J104.B4 J104.B9 R84.1 | length 338
  Top Layer w8: J104.A9@307.09,4181.17 J104.A9@307.09,4175.17 ; 310.21,4154.76 307.09,4157.89 J104.A9@307.09,4175.17 ; J104.B4@322.83,4175.17 J104.A9@307.09,4175.17 ; J104.A4@464.57,4175.17 J104.B9@480.31,4175.17 ; 480.31,4161.8 J104.B9@480.31,4175.17 ; J104.B9@480.31,4181.17 J104.B9@480.31,4175.17
  Top Layer w24: 439.53,4291.14 584.46,4291.14 613.16,4319.83 R84.1@687.11,4319.83
  other v1: 464.89,4227.42 325.12,4340 395,4340 464.89,4340
VBUS_DETECT: R85.2 R87.2 XDS1.1 | length 212.5
  Top Layer w8: R85.2@254.62,3202 R87.2@254.62,3255 361.65,3255 386.5,3279.85 XDS1.1@403.84,3279.85
VCCEN1: IC3.1 R77.2 TP2.1 XDS1.78 | length 2503.4
  Top Layer w8: v1(548.34,3578) 687.37,3717.03 XDS1.78@687.37,3886.15 ; TP2.1@1601,3301 1722,3422 1722,3472 1800,3550 1904,3550 R77.2@1932,3578 1964,3610 2090,3610 2110,3590 2110,3570 2127,3553 2201,3553 2220.4,3572.4 IC3.1@2220.4,3590
  Bottom Layer w8: v1(548.34,3578) 548.34,3351.66 599,3301 TP2.1@1601,3301
VCCEN2: XDS1.77
VREF: C26.2 U1.18 | length 118.9
  Top Layer w8: C26.2@871.91,1211.65 872.98,1210.58 872.98,1187.24 905.48,1154.74 U1.18@905.48,1106.66
XDS_DM: IC5.4 J104.A7 J104.B7 XDS1.93 | length 635.2
  Top Layer w8: IC5.4@372.05,4054.59 372.11,4054.65 372.11,4078.3 378.38,4084.58 378.38,4104.25 v4(379.53,4105.39) ; XDS1.93@451.15,3886.15 451.15,3831.69 463.28,3819.56 v4(463.28,3819)
  Top Layer w9.6: J104.B7@370.37,4175.46 370.37,4206.04 375.99,4211.66 411.77,4211.66 417.4,4206.04 417.4,4181.25 J104.A7@417.32,4181.17 ; J104.B7@370.58,4174.67 370.58,4141.55 379.53,4132.61 v4(379.53,4105.39)
  Bottom Layer w9.6: v4(379.53,4105.39) 379.53,4102.09 370,4092.57 370,4002.99 449.72,3923.28 449.72,3832.65 463.28,3819.09 v4(463.28,3819)
XDS_DP: IC5.5 J104.A6 J104.B6 XDS1.94 | length 686.9
  Top Layer w8: v4(344.88,4105.39) 346.37,4103.9 346.37,4084.34 352.36,4078.35 IC5.5@352.36,4054.59 ; v4(423.28,3819) 423.28,3819.56 435.4,3831.69 XDS1.94@435.4,3886.15
  Top Layer w9.6: v4(344.88,4105.39) 344.88,4133.86 354.28,4143.26 354.28,4175.13 354.33,4175.17 354.33,4192 354.77,4192.44 354.77,4212.5 369.53,4227.26 418.23,4227.26 433,4212.5 433,4181.25 J104.A6@433.07,4181.17
  Bottom Layer w9.6: v4(344.88,4105.39) 344.88,4102.09 354.4,4092.57 354.4,3996.53 434.12,3916.82 434.12,3831.82 423.28,3820.98 v4(423.28,3819)
XDS_GND: C37.2 C38.2 C39.2 C40.2 C41.2 C42.2 C43.2 C44.2 C45.2 C46.2 C47.2 C48.2 C49.2 C50.2 C51.2 C52.2 C53.2 C54.2 C55.2 C56.2 C57.2 C58.2 C59.2 C60.2 C61.1 C62.2 C63.2 C64.2 C65.2 C66.2 C67.1 C68.2 C69.2 C70.2 C71.2 D2.1 D2.2 IC2.1 IC3.2 IC4.4 IC5.3 IC6.4 IC6.9 J101.1 J102.3 J102.5 J102.7 J102.9 J104.1 J104.2 J104.3 J104.4 J104.A1 J104.A12 J104.B1 J104.B12 LED101.2 LED102.2 R52.2 R53.2 R54.2 R55.2 R60.1 R65.1 R72.1 R74.1 R77.1 R80.1 R81.1 R82.1 R86.1 R87.1 R88.1 TP4.1 XDS1.10 XDS1.17 XDS1.48 XDS1.55 XDS1.58 XDS1.64 XDS1.66 XDS1.80 XDS1.114 XDS2.13 XDS2.14 XDS2.17 Y3.2 Y3.4 | length 9145.9
  Top Layer w8: 171,3998.38 171,3958.38 C37.2@207.38,3922 ; R87.1@207.38,3255 174.5,3255 ; C42.2@207.38,3732.61 207.38,3576 C43.2@206.38,3575 206.38,3547 ; J104.A12@275.59,4175.17 J104.B1@291.34,4175.17 ; XDS1.114@344.85,3559.38 291.59,3559.38 279.21,3547 206.38,3547 ; 372.05,4002.91 IC5.3@372.05,4030.97 ; C54.2@452.72,4014.62 496.82,4014.62 Y3.4@511.69,4029.5 511.69,4042.9 C53.2@550.75,4081.97 587.18,4118.39 642.22,4118.39 ; J104.A1@496.06,4175.17 J104.B12@511.81,4175.17 ; XDS1.10@545.64,3279.85 545.64,3245.66 551.91,3239.39 645.68,3239.39 650.78,3244.49 ; Y3.2@598.31,3966.5 639.98,3966.5 642.22,3968.74 ; XDS1.17@655.87,3279.85 655.87,3249.58 650.78,3244.49 ; XDS1.80@655.87,3886.15 655.87,3945.2 642.22,3958.85 642.22,3968.74 ; XDS1.66@876.35,3886.15 876.35,3921.02 913,3957.68 913,4008.23 901.12,4020.11 889.51,4020.11 C38.2@882,4027.62 828,4027.62 828,4076.77 785.66,4119.1 v1(780.34,4119.1) 779.58,4118.34 642.22,4118.34 642.22,3968.74 ; XDS1.48@951.15,3575.13 905.45,3575.13 868.12,3537.79 844.96,3537.79 838,3544.75 838,3686 ; XDS1.55@951.15,3685.36 838.64,3685.36 838,3686 ; XDS1.58@951.15,3732.61 838.61,3732.61 838,3732 ; XDS1.64@951.15,3827.22 858.22,3827.22 838,3807 v1(838,3780) 838,3732 ; C39.2@1098.29,3563 C52.2@1098.29,3933 ; C40.2@1109.62,3621 C40.2@1110.13,3620.5 ; R60.1@1109.62,3673 v1(1210,3673) v1(1330,3673) 1414.38,3673 C58.2@1428.38,3687 ; v1(1423.8,2986.35) 1500.62,2986.35 IC4.4@1518.56,3004.29 ; R74.1@1428.38,3418 C59.2@1428.38,3472 1382,3518.38 1382,3591.5 1424.5,3634 R72.1@1428.38,3634 C58.2@1428.38,3687 ; v2(1557,3858) 1551.41,3858 1505.88,3812.47 1505.88,3812.25 1495.47,3801.83 1495.24,3801.83 1428.38,3734.97 C58.2@1428.38,3687 ; C55.2@1717,3914.24 1751,3880.24 1751,3832.24 R65.1@1717,3798.24 v1(1803,3712.24) 1830.89,3684.35 C66.2@1883.38,3684.35 1884.38,3683.35 C68.2@1884.38,3631 ; v1(1810.75,3578) R77.1@1884.76,3578 ; D2.2@1996.6,3722.41 v1(1996.6,3748) D2.1@1996.6,3773.59 ; 174.5,3255 83.49,3163.98 v1(78.35,3163.98) 78.35,3071.16 76.47,3069.29 LED102.2@76.47,2989 125.47,2940 J101.1@441.04,2940 441.04,3089.98 467.5,3116.44 C41.2@467.5,3120.38 C45.2@524,3120.38 524,3108 552,3080 596.99,3080 C50.2@638,3121.01 C51.2@695,3121.01 718.01,3098 779,3098 800.75,3076.25 834.95,3076.25 IC2.1@836.63,3074.57 838.32,3076.25 859.29,3076.25 897,3113.96 C46.2@897,3119.76 802.76,3214 v1(770,3214) 681.27,3214 650.78,3244.49 ; 174.5,3255 174.5,3356.5 180,3362 R82.1@207.38,3362 206.38,3363 C48.2@206.38,3468 C47.2@206.38,3521 206.38,3547 ; 838,3686 838,3732
  Top Layer w16: IC6.9@1063.84,4284.85 1063.84,4289.78 1097.3,4323.24 IC6.4@1118.95,4323.24 1374.83,4323.24 1610.06,4088.01 1622.64,4088.01 1642.2,4068.45 C56.2@1642.2,4060.58 ; 1076.43,4229.44 1076.43,4174.34 1087.66,4163.11 C71.2@1119.97,4163.11 ; v2(1557,3858) 1595.39,3896.39 XDS2.13@1595.39,3932.8 1586,3932.8 ; XDS2.14@1569.8,3932.8 1586,3932.8 ; R80.1@1875.5,3910.41 1725.34,4060.58 C56.2@1642.2,4060.58 ; R81.1@1931.24,3523 1931.24,3528 1981.38,3528 C63.2@1997,3543.62 2012.87,3559.5 C64.2@2070,3559.5 2101.5,3528 2171,3528 2180,3519 2180,3457.39 2159.38,3436.76 C65.2@2159.38,3434 2124,3434 v3(2100,3410) ; C62.2@2165.38,4039 2165.38,4085.99 C61.1@2146.5,4104.87 2146.5,4127.68 C60.2@2093.18,4181 2037.1,4124.92 1706.54,4124.92 C56.2@1642.2,4060.58 ; IC3.2@2183,3590 v3(2183,3629) 2183,3638.5 C67.1@2208.5,3664 ; 1586,3932.8 1589,3935.8 C57.2@1589,3983 1589,4007.38 C56.2@1642.2,4060.58
  Top Layer w20: J102.3@1750,2974.88 J102.5@1800,2974.88 J102.7@1850,2974.88 J102.9@1900,2974.88 v1(1983.12,2974.88)
  other v1: 2092.37,3040 1097.68,3055.97 955.5,3236.35 1023.59,3236.35 1100.65,3236.35 1912.66,3267.25 49.5,3290 1773.94,3392.69 1343.57,3469.38 780.01,3480.64 660,3629.32 749.88,3779.85 1212.7,3891.98 971.31,4002.91 1724.24,4100.17 230.69,4108.5 117.77,4191.63 2255.75,4238.3 1842.84,4332.6 2096.97,4399.25
  other v2: 1557,3814.69 1513.69,3858 1600.31,3858 1557,3901.31 1063.84,4260.25 1044.15,4284.85 1083.52,4284.85 1063.84,4309.46
XDS_ID: XDS1.95
XDS_RESET_OUT: IC4.2 J101.11 J102.10 R83.1 XDS1.40 | length 2087.2
  Top Layer w8: v1(900,3049.5) 930,3079.5 930,3200.5 910,3220.5 910,3439.5 919.65,3449.14 XDS1.40@951.15,3449.14 1043.87,3449.14 1048.56,3453.83 1048.56,3455.82 1056.37,3463.63 R83.1@1060.31,3463.63 ; IC4.2@1491.99,3029.88 1442.09,3029.88 1418.72,3053.25 v1(1418.72,3181.46) 1476.26,3239 1868,3239 1900,3207 J102.10@1900,3135.12
  Bottom Layer w8: J101.11@941.04,2940 900,2981.04 v1(900,3049.5) 1048.5,3198 1402.18,3198 v1(1418.72,3181.46)
XDS_RXD: J101.9 XDS1.33 | length 517.7
  Top Layer w8: J101.9@841.04,2940 879.19,2940 939.19,3000 971.18,3000 990,3018.82 990,3299.99 951.21,3338.78 XDS1.33@951.15,3338.78
XDS_TCK_SWDCLK: IC4.6 J101.15 J102.4 XDS1.35 | length 1706.1
  Top Layer w8: XDS1.35@951.15,3370.4 1094.82,3370.4 1142.58,3322.64 J101.15@1142.58,2941.54 ; v1(1490,2939) 1500.93,2949.93 1549.85,2949.93 1570,2970.08 1570,3022 1562.12,3029.88 IC4.6@1545.14,3029.88 ; v1(1710,3051) 1736,3051 1750,3065 J102.4@1750,3135.12
  Bottom Layer w8: J101.15@1141.04,2940 1305.64,3104.61 1490,3104.61 ; v1(1490,2939) 1490,3104.61 ; v1(1710,3051) 1672,3051 1618.39,3104.61 1490,3104.61
XDS_TDI: IC4.3 J102.8 XDS1.38 | length 1505.7
  Top Layer w8: XDS1.38@951.15,3417.65 1128.16,3417.65 1169.2,3458.68 1262.15,3458.68 1355.89,3364.95 v1(1355.89,3153.31) 1355.89,3089.08 1355,3088.2 1432.85,3010.35 1491.83,3010.35 IC4.3@1491.99,3010.19 ; v1(1520.04,3185) 1554.04,3219 1839,3219 1850,3208 J102.8@1850,3135.12
  Bottom Layer w8: v1(1355.89,3153.31) 1488.35,3153.31 v1(1520.04,3185)
XDS_TDO_SWO: IC4.5 J102.6 XDS1.37 | length 1668.4
  Top Layer w8: XDS1.37@951.15,3401.9 1132.21,3401.9 1169.65,3439.34 1229.82,3439.34 1255,3414.15 v1(1255,3158.17) 1255,3107.86 1406.86,2956 1469,2956 1483.31,2970.31 1525.31,2970.31 1545.14,2990.14 IC4.5@1545.14,3010.19 ; v1(1601,3179) 1623.85,3201.85 1773.94,3201.85 1800,3175.79 J102.6@1800,3135.12
  Bottom Layer w8: v1(1255,3158.17) 1293.13,3158.17 1329.96,3121.34 1543.34,3121.34 v1(1601,3179)
XDS_TMS_SWDIO: IC4.7 J101.13 J102.2 XDS1.36 | length 1610.7
  Top Layer w8: XDS1.36@951.15,3386.15 1132.63,3386.15 1185.04,3333.75 v1(1185.04,3076.4) ; J101.13@1055,2940 1097.39,2897.61 1488.61,2897.61 1521,2930 1563,2930 1591,2958 1591,3049.56 ; IC4.7@1545.14,3049.56 1591,3049.56 ; J102.2@1700,3135.12 1700,3115 1634.56,3049.56 1591,3049.56
  Bottom Layer w8: J101.13@1041.04,2940 1041.04,2944.12 1118.38,3021.47 1161.58,3021.47 1161.73,3021.31 1168.36,3021.31 1185.04,3037.99 v1(1185.04,3076.4)
XDS_TXD: J101.7 XDS1.34 | length 719.8
  Top Layer w8: J101.7@755,2940 833,3018 918,3018 v1(950,3050) ; XDS1.34@951.15,3354.65 1014.6,3354.65 ; 1014.6,3354.53 1014.73,3354.53 1060,3309.25 1060,3080 v1(1030,3050)
  Bottom Layer w8: v1(950,3050) v1(1030,3050)
XDS_VBUS: C60.1 C61.2 C62.1 C69.1 C70.1 IC5.6 IC6.5 IC6.8 J101.3 R56.1 R76.2 R84.2 R85.1 T1.2 | length 4984.7
  Top Layer w8: v1(207.38,3155.21) R85.1@207.38,3202 ; R56.1@207.66,3975.28 204.81,3978.14 204.81,3994.68 165.97,4033.52 v1(165.97,4072.28) 292.71,4072.28 312.3,4052.69 332.61,4052.69 332.68,4052.75 IC5.6@332.68,4054.59
  Top Layer w16: R84.2@750.11,4319.83 C69.1@833.93,4319.83 ; C69.1@826.42,4317.64 826.22,4317.84 826.22,4385.02 v1(826.02,4385.22) 1356.93,4385.22 1561.15,4181 C60.1@1990.82,4181 1990.82,4195.82 2030,4235 2123.49,4235 2219,4139.49 2219,3917.82 T1.2@2154,3852.82 ; C69.1@835.15,4320.67 919.85,4320.67 C70.1@921.91,4322.72 ; C70.1@922.91,4323.73 967.41,4323.73 ; IC6.8@1008.72,4246.47 976.42,4246.47 967.04,4255.84 967.04,4323.37 967.41,4323.73 ; IC6.5@1008.72,4323.24 1008.23,4323.73 967.41,4323.73
  Bottom Layer w24: J101.3@541.04,2940 325.83,3155.21 153.87,3155.21 119.43,3189.65 119.43,3741.43 165.97,3787.97 v1(165.97,4072.28) 165.97,4233.48 224.05,4291.56 792.85,4291.56 826.02,4324.74 v1(826.02,4385.22)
